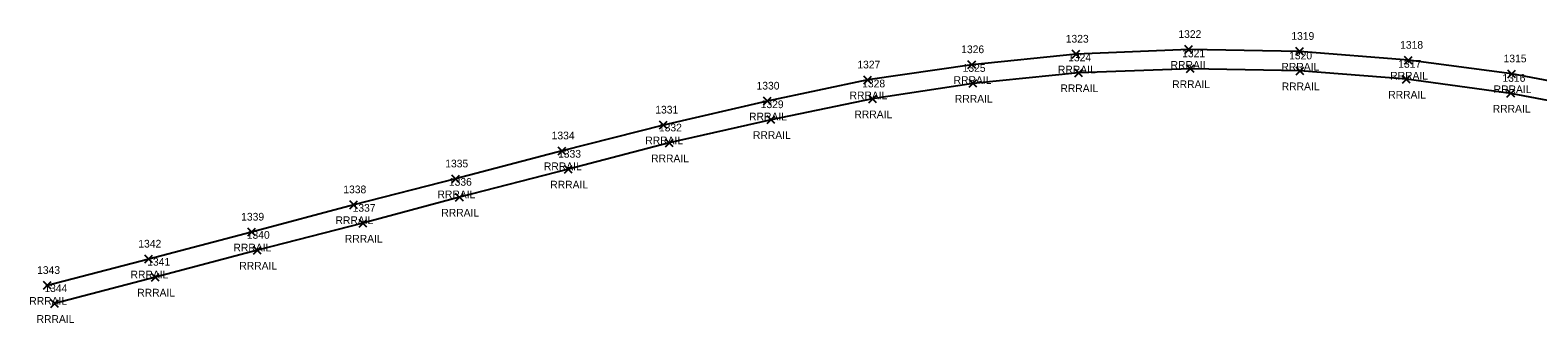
# Model space of a CAD drawing. Extents: x 1715662 to 1717487, y 887396 to 890004.
# Drawn here: x 1715662 to 1716052.9, y 888478.2 to 888554.2 of the extents above; entities that cross this region are included whole.
import ezdxf

# ---------------------------------------------------------------- set-up
doc = ezdxf.new("R2010")
doc.units = 0
for name, color, linetype in [('R_A', 7, 'Continuous'), ('R_I', 7, 'Continuous'), ('R_TIC', 7, 'Continuous'), ('RR', 7, 'Continuous')]:
    doc.layers.add(name, color=color, linetype=linetype)

msp = doc.modelspace()

# ---------------------------------------------------------------- linework, layer by layer
at = {"layer": 'R_TIC'}
for points in [[(1715932.18, 888546.95), (1715934.18, 888548.95)], [(1715934.18, 888546.95), (1715932.18, 888548.95)], [(1715961.39, 888548.16), (1715963.39, 888550.16)], [(1715963.39, 888548.16), (1715961.39, 888550.16)], [(1715990.12, 888547.67), (1715992.12, 888549.67)], [(1715992.12, 888547.67), (1715990.12, 888549.67)], [(1716018.33, 888545.36), (1716020.33, 888547.36)], [(1716020.33, 888545.36), (1716018.33, 888547.36)], [(1715905.14, 888544.21), (1715907.14, 888546.21)], [(1715907.14, 888544.21), (1715905.14, 888546.21)], [(1715932.82, 888542.09), (1715934.82, 888544.09)], [(1715934.82, 888542.09), (1715932.82, 888544.09)], [(1715961.8, 888543.15), (1715963.8, 888545.15)], [(1715963.8, 888543.15), (1715961.8, 888545.15)], [(1715990.2, 888542.6), (1715992.2, 888544.6)], [(1715992.2, 888542.6), (1715990.2, 888544.6)], [(1716045.15, 888541.83), (1716047.15, 888543.83)], [(1716047.15, 888541.83), (1716045.15, 888543.83)], [(1715878.15, 888540.25), (1715880.15, 888542.25)], [(1715880.15, 888540.25), (1715878.15, 888542.25)], [(1715905.45, 888539.37), (1715907.45, 888541.37)], [(1715907.45, 888539.37), (1715905.45, 888541.37)], [(1716017.82, 888540.43), (1716019.82, 888542.43)], [(1716019.82, 888540.43), (1716017.82, 888542.43)], [(1716044.9, 888536.78), (1716046.9, 888538.78)], [(1716046.9, 888536.78), (1716044.9, 888538.78)], [(1715852.1, 888534.77), (1715854.1, 888536.77)], [(1715854.1, 888534.77), (1715852.1, 888536.77)], [(1715879.4, 888535.33), (1715881.4, 888537.33)], [(1715881.4, 888535.33), (1715879.4, 888537.33)], [(1715853.1, 888529.95), (1715855.1, 888531.95)], [(1715855.1, 888529.95), (1715853.1, 888531.95)], [(1715825.19, 888528.55), (1715827.19, 888530.55)], [(1715827.19, 888528.55), (1715825.19, 888530.55)], [(1715798.9, 888521.85), (1715800.9, 888523.85)], [(1715800.9, 888521.85), (1715798.9, 888523.85)], [(1715826.7, 888523.91), (1715828.7, 888525.91)], [(1715828.7, 888523.91), (1715826.7, 888525.91)], [(1715800.55, 888517.1), (1715802.55, 888519.1)], [(1715802.55, 888517.1), (1715800.55, 888519.1)], [(1715771.3, 888514.57), (1715773.3, 888516.57)], [(1715773.3, 888514.57), (1715771.3, 888516.57)], [(1715772.3, 888509.81), (1715774.3, 888511.81)], [(1715774.3, 888509.81), (1715772.3, 888511.81)], [(1715744.87, 888507.86), (1715746.87, 888509.86)], [(1715746.87, 888507.86), (1715744.87, 888509.86)], [(1715747.28, 888503.07), (1715749.28, 888505.07)], [(1715749.28, 888503.07), (1715747.28, 888505.07)], [(1715718.4, 888500.77), (1715720.4, 888502.77)], [(1715720.4, 888500.77), (1715718.4, 888502.77)], [(1715691.72, 888493.77), (1715693.72, 888495.77)], [(1715693.72, 888493.77), (1715691.72, 888495.77)], [(1715719.92, 888496.05), (1715721.92, 888498.05)], [(1715721.92, 888496.05), (1715719.92, 888498.05)], [(1715665.47, 888486.93), (1715667.47, 888488.93)], [(1715667.47, 888486.93), (1715665.47, 888488.93)], [(1715693.46, 888489.07), (1715695.46, 888491.07)], [(1715695.46, 888489.07), (1715693.46, 888491.07)], [(1715667.36, 888482.23), (1715669.36, 888484.23)], [(1715669.36, 888482.23), (1715667.36, 888484.23)]]:
    msp.add_lwpolyline(points, dxfattribs=at)
at = {"layer": 'RR'}
for points in [[(1716073.49, 888537.69), (1716046.15, 888542.83), (1716019.33, 888546.36), (1715991.12, 888548.67), (1715962.39, 888549.16), (1715933.18, 888547.95), (1715906.14, 888545.21), (1715879.15, 888541.25), (1715853.1, 888535.77), (1715826.19, 888529.55), (1715799.9, 888522.85), (1715772.3, 888515.57), (1715745.87, 888508.86), (1715719.4, 888501.77), (1715692.72, 888494.77), (1715666.47, 888487.93)], [(1716072.38, 888532.71), (1716045.9, 888537.78), (1716018.82, 888541.43), (1715991.2, 888543.6), (1715962.8, 888544.15), (1715933.82, 888543.09), (1715906.45, 888540.37), (1715880.4, 888536.33), (1715854.1, 888530.95), (1715827.7, 888524.91), (1715801.55, 888518.1), (1715773.3, 888510.81), (1715748.28, 888504.07), (1715720.92, 888497.05), (1715694.46, 888490.07), (1715668.36, 888483.23)]]:
    msp.add_lwpolyline(points, dxfattribs=at)

# ---------------------------------------------------------------- texts
at = {"layer": 'R_A'}
for p in [(1715928.47, 888542.95), (1715957.69, 888544.16), (1715986.41, 888543.67), (1716014.62, 888541.36), (1715901.43, 888540.21), (1715929.11, 888538.09), (1715958.1, 888539.15), (1715986.49, 888538.6), (1716041.44, 888537.83), (1715874.44, 888536.25), (1715901.74, 888535.37), (1716014.11, 888536.43), (1716041.2, 888532.78), (1715848.39, 888530.77), (1715875.69, 888531.33), (1715849.39, 888525.95), (1715821.48, 888524.55), (1715795.19, 888517.85), (1715822.99, 888519.91), (1715767.59, 888510.57), (1715796.84, 888513.1), (1715768.59, 888505.81), (1715741.16, 888503.86), (1715743.57, 888499.07), (1715714.69, 888496.77), (1715688.01, 888489.77), (1715716.21, 888492.05), (1715661.76, 888482.93), (1715689.75, 888485.07), (1715663.65, 888478.23)]:
    msp.add_text('RRRAIL', height=2, dxfattribs=at).set_placement(p)
at = {"layer": 'R_I'}
for s, p in [('1323', (1715930.49, 888550.95)), ('1322', (1715959.7, 888552.16)), ('1319', (1715988.99, 888551.67)), ('1318', (1716017.2, 888549.36)), ('1326', (1715903.39, 888548.21)), ('1324', (1715931.12, 888546.09)), ('1321', (1715960.68, 888547.15)), ('1320', (1715988.42, 888546.6)), ('1317', (1716016.7, 888544.43)), ('1315', (1716044.02, 888545.83)), ('1327', (1715876.46, 888544.25)), ('1325', (1715903.76, 888543.37)), ('1316', (1716043.72, 888540.78)), ('1330', (1715850.32, 888538.77)), ('1328', (1715877.71, 888539.33)), ('1329', (1715851.4, 888533.95)), ('1331', (1715824.07, 888532.55)), ('1334', (1715797.2, 888525.85)), ('1332', (1715825.01, 888527.91)), ('1333', (1715798.86, 888521.1)), ('1335', (1715769.61, 888518.57)), ('1336', (1715770.55, 888513.81)), ('1338', (1715743.18, 888511.86)), ('1337', (1715745.59, 888507.07)), ('1339', (1715716.69, 888504.77)), ('1342', (1715690.02, 888497.77)), ('1340', (1715718.14, 888500.05)), ('1343', (1715663.78, 888490.93)), ('1341', (1715692.34, 888493.07)), ('1344', (1715665.67, 888486.23))]:
    msp.add_text(s, height=2, dxfattribs=at).set_placement(p)

doc.saveas('drawing.dxf')
